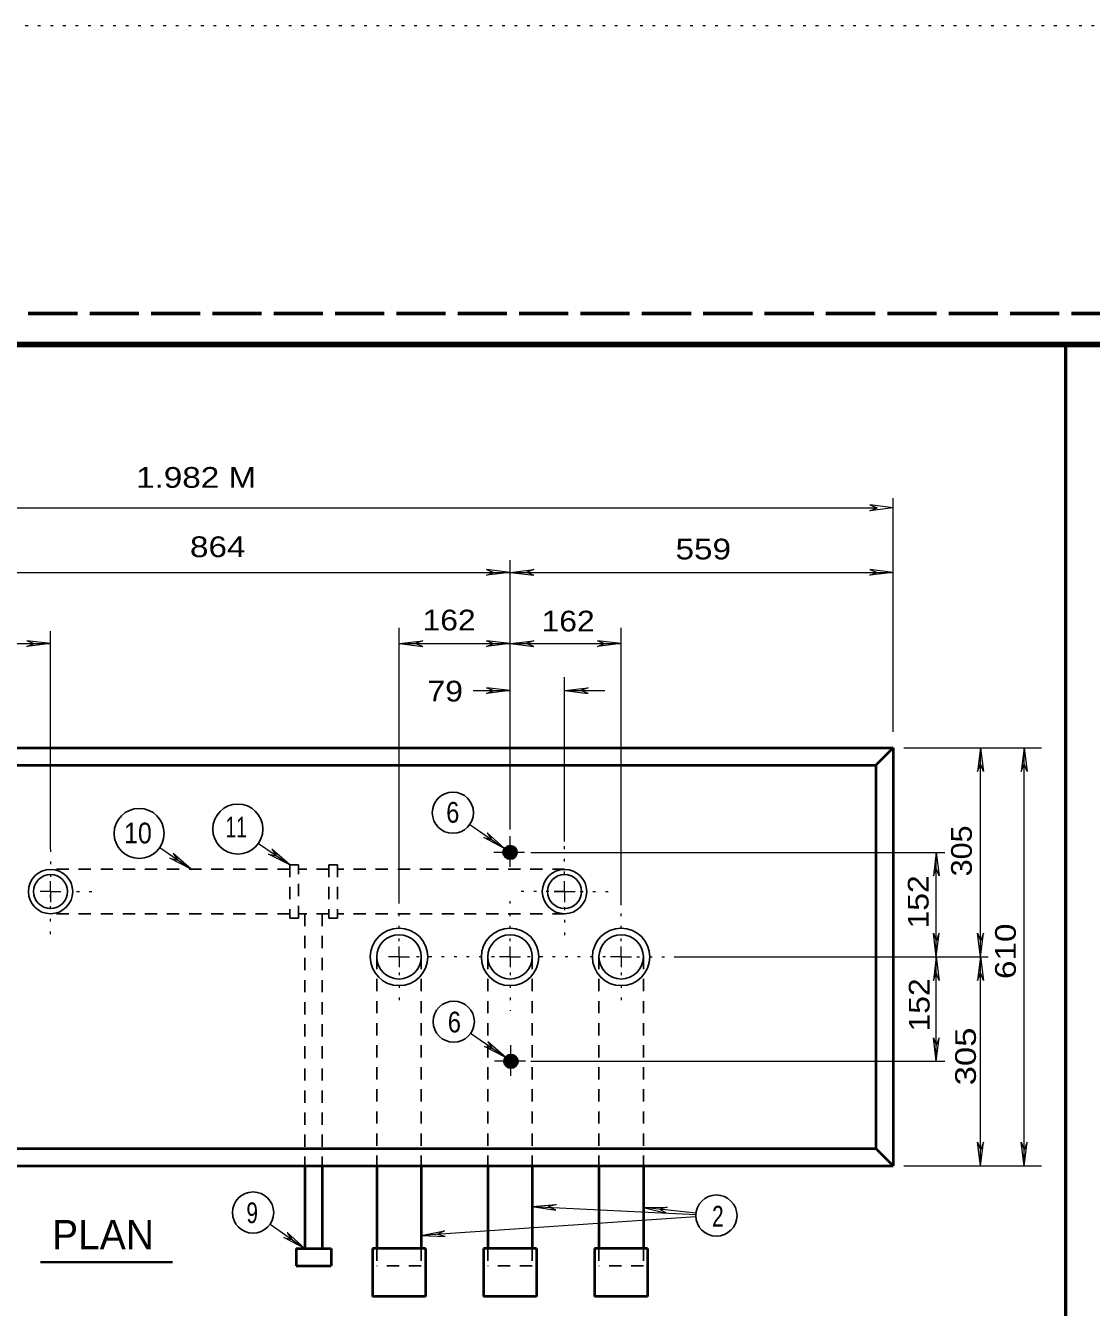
# Model space of a CAD drawing. Extents: x 312583 to 312854, y 144419 to 144597.
# Drawn here: x 312674.35 to 312713.43, y 144549.76 to 144596.78 of the extents above; entities that cross this region are included whole.
import ezdxf
from ezdxf.enums import TextEntityAlignment as Align

# ---------------------------------------------------------------- set-up
doc = ezdxf.new("R2010")
doc.units = 0
doc.header["$LTSCALE"] = 0.3
for name, pattern in [('DOTTED', [1.5, 0.3, -1.2]), ('LONG_DASHED', [7.5, 6, -1.5]), ('SHORT_DASHED', [2.7, 1.5, -1.2])]:
    doc.linetypes.add(name, pattern=pattern)
for name, color, linetype, lineweight in [('1', 7, 'Continuous', 25), ('2', 7, 'Continuous', 13), ('63', 7, 'DOTTED', 13)]:
    doc.layers.add(name, color=color, linetype=linetype, lineweight=lineweight)

msp = doc.modelspace()

# ---------------------------------------------------------------- linework, layer by layer
at = {"layer": '1', "linetype": 'LONG_DASHED', "lineweight": 60}
msp.add_line((312851.75, 144586.2246), (312583.526, 144586.2246), dxfattribs=at)
at = {"layer": '1', "lineweight": 53}
msp.add_line((312712.4965, 144506.4889), (312712.4965, 144585.0846), dxfattribs=at)
at = {"layer": '1', "lineweight": 40}
for p, q in [((312656.3351, 144570.2833), (312706.1684, 144570.2833)), ((312705.5321, 144569.6469), (312706.1684, 144570.2833)), ((312706.1684, 144570.2833), (312706.1684, 144554.9499)), ((312656.9791, 144569.6469), (312705.5321, 144569.6469)), ((312705.5321, 144569.6469), (312705.5321, 144555.5863)), ((312656.9791, 144555.5863), (312705.5321, 144555.5863)), ((312705.5321, 144555.5863), (312706.1684, 144554.9499)), ((312656.3351, 144554.9499), (312706.1684, 144554.9499)), ((312684.5944, 144554.9499), (312684.5944, 144551.9139)), ((312685.2307, 144554.9499), (312685.2307, 144551.9139)), ((312687.2317, 144554.9499), (312687.2317, 144551.9139)), ((312688.8571, 144554.9499), (312688.8571, 144551.9139)), ((312691.3027, 144554.9499), (312691.3027, 144551.9139)), ((312692.9281, 144554.9499), (312692.9281, 144551.9139)), ((312695.3737, 144554.9499), (312695.3737, 144551.9139)), ((312697.0067, 144554.9499), (312697.0067, 144551.9139)), ((312684.2724, 144551.9139), (312685.5527, 144551.9139)), ((312684.2724, 144551.9139), (312684.2724, 144551.2776)), ((312685.5527, 144551.9139), (312685.5527, 144551.2776)), ((312687.0707, 144551.9139), (312687.0707, 144550.1583)), ((312689.0181, 144551.9139), (312687.0707, 144551.9139)), ((312689.0181, 144551.9139), (312689.0181, 144550.1583)), ((312691.1417, 144551.9139), (312691.1417, 144550.1583)), ((312693.0891, 144551.9139), (312691.1417, 144551.9139)), ((312693.0891, 144551.9139), (312693.0891, 144550.1583)), ((312695.2127, 144551.9139), (312695.2127, 144550.1583)), ((312697.1601, 144551.9139), (312695.2127, 144551.9139)), ((312697.1601, 144551.9139), (312697.1601, 144550.1583)), ((312684.2724, 144551.2776), (312685.5527, 144551.2776)), ((312689.0181, 144550.1583), (312687.0707, 144550.1583)), ((312693.0891, 144550.1583), (312691.1417, 144550.1583)), ((312697.1601, 144550.1583), (312695.2127, 144550.1583))]:
    msp.add_line(p, q, dxfattribs=at)
at = {"layer": '1', "linetype": 'SHORT_DASHED'}
for p, q in [((312684.0347, 144565.8289), (312675.2641, 144565.8289)), ((312684.0347, 144565.9899), (312684.0347, 144564.0349)), ((312684.0347, 144565.9899), (312684.3567, 144565.9899)), ((312684.3567, 144565.9899), (312684.3567, 144565.8289)), ((312684.3567, 144564.0349), (312684.3567, 144565.8289)), ((312685.4684, 144565.8289), (312684.3567, 144565.8289)), ((312685.4684, 144565.9899), (312685.4684, 144564.1959)), ((312685.4684, 144565.9899), (312685.7904, 144565.9899)), ((312685.7904, 144565.9899), (312685.7904, 144564.0349)), ((312694.1164, 144565.8289), (312685.7904, 144565.8289)), ((312684.0347, 144564.1959), (312675.2641, 144564.1959)), ((312684.0347, 144564.0349), (312684.3567, 144564.0349)), ((312685.4684, 144564.1959), (312684.3567, 144564.1959)), ((312684.5944, 144564.1959), (312684.5944, 144554.9499)), ((312685.2307, 144564.1959), (312685.2307, 144554.9499)), ((312685.4684, 144564.0349), (312685.4684, 144564.1959)), ((312685.4684, 144564.0349), (312685.7904, 144564.0349)), ((312694.1164, 144564.1959), (312685.7904, 144564.1959)), ((312687.2317, 144562.6166), (312687.2317, 144554.9499)), ((312688.8571, 144562.6166), (312688.8571, 144554.9499)), ((312691.3027, 144562.6166), (312691.3027, 144554.9499)), ((312692.9281, 144562.6166), (312692.9281, 144554.9499)), ((312695.3737, 144562.6166), (312695.3737, 144554.9499)), ((312697.0067, 144562.6166), (312697.0067, 144554.9499)), ((312687.2317, 144551.9139), (312687.2317, 144551.2776)), ((312688.8571, 144551.9139), (312688.8571, 144551.2776)), ((312691.3027, 144551.9139), (312691.3027, 144551.2776)), ((312692.9281, 144551.9139), (312692.9281, 144551.2776)), ((312695.3737, 144551.9139), (312695.3737, 144551.2776)), ((312697.0067, 144551.9139), (312697.0067, 144551.2776)), ((312688.8571, 144551.2776), (312687.2317, 144551.2776)), ((312692.9281, 144551.2776), (312691.3027, 144551.2776)), ((312697.0067, 144551.2776), (312695.3737, 144551.2776))]:
    msp.add_line(p, q, dxfattribs=at)
at = {"layer": '1', "lineweight": 158}
msp.add_lwpolyline([(312616.5, 144423.1446), (312616.5, 144585.0846), (312849, 144585.0846)], dxfattribs=at)
at = {"layer": '1', "lineweight": 40}
for centre, radius in [((312692.116, 144566.4493), 0.2396), ((312692.116, 144566.4493), 0.2156), ((312692.116, 144566.4493), 0.1941), ((312692.116, 144566.4493), 0.1747), ((312692.116, 144566.4493), 0.1572), ((312692.116, 144566.4493), 0.1415), ((312692.116, 144566.4493), 0.1273), ((312692.116, 144566.4493), 0.1146), ((312692.116, 144566.4493), 0.1031), ((312692.116, 144566.4493), 0.0928), ((312692.116, 144566.4493), 0.0835), ((312692.116, 144566.4493), 0.0752), ((312692.116, 144566.4493), 0.0677), ((312692.116, 144566.4493), 0.0609), ((312692.116, 144566.4493), 0.0548), ((312692.148, 144558.7826), 0.2396), ((312692.148, 144558.7826), 0.2156), ((312692.148, 144558.7826), 0.1941), ((312692.148, 144558.7826), 0.1747), ((312692.148, 144558.7826), 0.1572), ((312692.148, 144558.7826), 0.1415), ((312692.148, 144558.7826), 0.1273), ((312692.148, 144558.7826), 0.1146), ((312692.148, 144558.7826), 0.1031), ((312692.148, 144558.7826), 0.0928), ((312692.148, 144558.7826), 0.0835), ((312692.148, 144558.7826), 0.0752), ((312692.148, 144558.7826), 0.0677), ((312692.148, 144558.7826), 0.0609), ((312692.148, 144558.7826), 0.0548)]:
    msp.add_circle(centre, radius, dxfattribs=at)
at = {"layer": '1'}
for centre, radius in [((312675.2653, 144565.0118), 0.8146), ((312694.1126, 144565.0118), 0.8146), ((312675.2653, 144565.0118), 0.6232), ((312694.1126, 144565.0118), 0.6232), ((312688.0431, 144562.616), 1.0542), ((312692.116, 144562.616), 1.0542), ((312696.189, 144562.616), 1.0542), ((312688.0431, 144562.616), 0.8146), ((312692.116, 144562.616), 0.8146), ((312696.189, 144562.616), 0.8146)]:
    msp.add_circle(centre, radius, dxfattribs=at)
at = {"layer": '2'}
for p, q in [((312706.1684, 144570.8736), (312706.1684, 144579.4526)), ((312656.3351, 144579.0923), (312705.5321, 144579.0923)), ((312705.3021, 144579.1996), (312705.5781, 144579.0923)), ((312706.1684, 144579.0923), (312705.3021, 144579.1996)), ((312705.3021, 144578.9849), (312705.5781, 144579.0923)), ((312706.1684, 144579.0923), (312705.3021, 144578.9849)), ((312692.1154, 144567.2856), (312692.1154, 144577.1679)), ((312670.3957, 144576.7233), (312692.1154, 144576.7233)), ((312691.2491, 144576.8306), (312691.5251, 144576.7233)), ((312692.1154, 144576.7233), (312691.2491, 144576.8306)), ((312691.2491, 144576.6159), (312691.5251, 144576.7233)), ((312692.1154, 144576.7233), (312691.2491, 144576.6159)), ((312692.1154, 144576.7233), (312692.9817, 144576.8306)), ((312692.1154, 144576.7233), (312706.1684, 144576.7233)), ((312692.1154, 144576.7233), (312692.9817, 144576.6159)), ((312692.9817, 144576.8306), (312692.7057, 144576.7233)), ((312692.9817, 144576.6159), (312692.7057, 144576.7233)), ((312705.3021, 144576.8306), (312705.5781, 144576.7233)), ((312706.1684, 144576.7233), (312705.3021, 144576.8306)), ((312705.3021, 144576.6159), (312705.5781, 144576.7233)), ((312706.1684, 144576.7233), (312705.3021, 144576.6159)), ((312675.2641, 144566.5726), (312675.2641, 144574.5613)), ((312688.0444, 144564.6023), (312688.0444, 144574.6916)), ((312696.1864, 144564.5179), (312696.1864, 144574.6916)), ((312670.3957, 144574.1089), (312675.2641, 144574.1089)), ((312674.3977, 144574.2163), (312674.6737, 144574.1089)), ((312675.2641, 144574.1089), (312674.3977, 144574.2163)), ((312674.3977, 144574.0016), (312674.6737, 144574.1089)), ((312675.2641, 144574.1089), (312674.3977, 144574.0016)), ((312688.0444, 144574.1089), (312688.9107, 144574.2163)), ((312688.0444, 144574.1089), (312688.9107, 144574.0016)), ((312688.0444, 144574.1089), (312692.1154, 144574.1089)), ((312688.9107, 144574.2163), (312688.6347, 144574.1089)), ((312688.9107, 144574.0016), (312688.6347, 144574.1089)), ((312691.2491, 144574.2163), (312691.5251, 144574.1089)), ((312692.1154, 144574.1089), (312691.2491, 144574.2163)), ((312691.2491, 144574.0016), (312691.5251, 144574.1089)), ((312692.1154, 144574.1089), (312691.2491, 144574.0016)), ((312692.1154, 144574.1089), (312692.9817, 144574.2163)), ((312692.1154, 144574.1089), (312696.1864, 144574.1089)), ((312692.1154, 144574.1089), (312692.9817, 144574.0016)), ((312692.9817, 144574.2163), (312692.7057, 144574.1089)), ((312692.9817, 144574.0016), (312692.7057, 144574.1089)), ((312695.3201, 144574.2163), (312695.5961, 144574.1089)), ((312696.1864, 144574.1089), (312695.3201, 144574.2163)), ((312695.3201, 144574.0016), (312695.5961, 144574.1089)), ((312696.1864, 144574.1089), (312695.3201, 144574.0016)), ((312694.1164, 144566.8486), (312694.1164, 144572.8823)), ((312691.2491, 144572.4913), (312691.5251, 144572.3839)), ((312692.1154, 144572.3839), (312691.2491, 144572.4913)), ((312694.1164, 144572.3839), (312694.9827, 144572.4913)), ((312694.9827, 144572.4913), (312694.7067, 144572.3839)), ((312690.7661, 144572.3839), (312692.1154, 144572.3839)), ((312691.2491, 144572.2766), (312691.5251, 144572.3839)), ((312692.1154, 144572.3839), (312691.2491, 144572.2766)), ((312694.1164, 144572.3839), (312695.5961, 144572.3839)), ((312694.1164, 144572.3839), (312694.9827, 144572.2766)), ((312694.9827, 144572.2766), (312694.7067, 144572.3839)), ((312706.5517, 144570.2833), (312711.5994, 144570.2833)), ((312709.3687, 144570.2833), (312709.2614, 144569.4169)), ((312709.3687, 144570.2833), (312709.476, 144569.4169)), ((312710.9675, 144570.2833), (312710.8602, 144569.4169)), ((312710.9675, 144570.2833), (312711.0748, 144569.4169)), ((312710.9675, 144554.9499), (312710.9675, 144570.2833)), ((312709.2614, 144569.4169), (312709.3687, 144569.6929)), ((312709.476, 144569.4169), (312709.3687, 144569.6929)), ((312710.8602, 144569.4169), (312710.9675, 144569.6929)), ((312711.0748, 144569.4169), (312710.9675, 144569.6929)), ((312690.6357, 144567.4773), (312691.9161, 144566.5879)), ((312682.8847, 144566.7796), (312684.0347, 144565.9899)), ((312691.1494, 144566.9943), (312691.4331, 144566.9253)), ((312691.9161, 144566.5879), (312691.1494, 144566.9943)), ((312691.2721, 144567.1706), (312691.4331, 144566.9253)), ((312691.9161, 144566.5879), (312691.2721, 144567.1706)), ((312692.1154, 144565.9209), (312692.1154, 144567.0479)), ((312679.2661, 144566.6263), (312680.4161, 144565.8289)), ((312679.7644, 144566.4116), (312679.9331, 144566.1663)), ((312680.4161, 144565.8289), (312679.7644, 144566.4116)), ((312683.2604, 144566.3886), (312683.5517, 144566.3196)), ((312684.0347, 144565.9899), (312683.2604, 144566.3886)), ((312683.3831, 144566.5649), (312683.5517, 144566.3196)), ((312684.0347, 144565.9899), (312683.3831, 144566.5649)), ((312692.6444, 144566.4499), (312691.5174, 144566.4499)), ((312692.8744, 144566.4499), (312708.0599, 144566.4499)), ((312707.7446, 144566.4499), (312707.6372, 144565.5836)), ((312707.7446, 144566.4499), (312707.8519, 144565.5836)), ((312679.6417, 144566.2353), (312679.9331, 144566.1663)), ((312680.4161, 144565.8289), (312679.6417, 144566.2353)), ((312707.6372, 144565.5836), (312707.7446, 144565.8596)), ((312707.8519, 144565.5836), (312707.7446, 144565.8596)), ((312675.2641, 144565.0086), (312675.2641, 144565.3919)), ((312694.1164, 144565.0086), (312694.1164, 144565.3919)), ((312675.2641, 144565.0086), (312674.8807, 144565.0086)), ((312675.2641, 144565.0086), (312675.6474, 144565.0086)), ((312675.2641, 144565.0086), (312675.2641, 144564.6253)), ((312694.1164, 144565.0086), (312694.4997, 144565.0086)), ((312694.1164, 144565.0086), (312694.1164, 144564.6253)), ((312707.6372, 144563.4829), (312707.7446, 144563.2069)), ((312707.7446, 144562.6166), (312707.6372, 144563.4829)), ((312707.8519, 144563.4829), (312707.7446, 144563.2069)), ((312707.7446, 144562.6166), (312707.8519, 144563.4829)), ((312709.2614, 144563.4829), (312709.3687, 144563.2069)), ((312709.3687, 144562.6166), (312709.2614, 144563.4829)), ((312709.476, 144563.4829), (312709.3687, 144563.2069)), ((312709.3687, 144562.6166), (312709.476, 144563.4829)), ((312688.0444, 144562.6166), (312688.0444, 144562.9999)), ((312692.1154, 144562.6166), (312692.1154, 144562.9999)), ((312696.1864, 144562.6166), (312696.1864, 144562.9999)), ((312688.0444, 144562.6166), (312687.6611, 144562.6166)), ((312688.0444, 144562.6166), (312688.4277, 144562.6166)), ((312688.0444, 144562.6166), (312688.0444, 144562.2333)), ((312692.1154, 144562.6166), (312691.7321, 144562.6166)), ((312692.1154, 144562.6166), (312692.4987, 144562.6166)), ((312692.1154, 144562.6166), (312692.1154, 144562.2333)), ((312696.1864, 144562.6166), (312695.8031, 144562.6166)), ((312696.1864, 144562.6166), (312696.5697, 144562.6166)), ((312696.1864, 144562.6166), (312696.1864, 144562.2333)), ((312698.1337, 144562.6166), (312709.6519, 144562.6166)), ((312707.7446, 144562.6166), (312707.6372, 144561.7503)), ((312707.7446, 144562.6166), (312707.8519, 144561.7503)), ((312709.3687, 144562.6166), (312709.2614, 144561.7503)), ((312709.3687, 144562.6166), (312709.476, 144561.7503)), ((312707.6372, 144561.7503), (312707.7446, 144562.0263)), ((312707.8519, 144561.7503), (312707.7446, 144562.0263)), ((312709.2614, 144561.7503), (312709.3687, 144562.0263)), ((312709.476, 144561.7503), (312709.3687, 144562.0263)), ((312690.6664, 144559.8106), (312691.9544, 144558.9213)), ((312691.1801, 144559.3276), (312691.4637, 144559.2586)), ((312691.9544, 144558.9213), (312691.1801, 144559.3276)), ((312691.3027, 144559.5039), (312691.4637, 144559.2586)), ((312691.9544, 144558.9213), (312691.3027, 144559.5039)), ((312692.1461, 144558.2543), (312692.1461, 144559.3813)), ((312707.6372, 144559.6496), (312707.7446, 144559.3736)), ((312707.7446, 144558.7833), (312707.6372, 144559.6496)), ((312707.8519, 144559.6496), (312707.7446, 144559.3736)), ((312707.7446, 144558.7833), (312707.8519, 144559.6496)), ((312692.6751, 144558.7833), (312691.5481, 144558.7833)), ((312692.8744, 144558.7833), (312708.0599, 144558.7833)), ((312709.2614, 144555.8163), (312709.3687, 144555.5403)), ((312709.3687, 144554.9499), (312709.2614, 144555.8163)), ((312709.476, 144555.8163), (312709.3687, 144555.5403)), ((312709.3687, 144554.9499), (312709.476, 144555.8163)), ((312710.8602, 144555.8163), (312710.9675, 144555.5403)), ((312710.9675, 144554.9499), (312710.8602, 144555.8163)), ((312710.8602, 144555.8163), (312710.9675, 144555.5403)), ((312710.9675, 144554.9499), (312710.8602, 144555.8163)), ((312711.0748, 144555.8163), (312710.9675, 144555.5403)), ((312710.9675, 144554.9499), (312711.0748, 144555.8163)), ((312711.0748, 144555.8163), (312710.9675, 144555.5403)), ((312710.9675, 144554.9499), (312711.0748, 144555.8163)), ((312706.5517, 144554.9499), (312711.5994, 144554.9499)), ((312692.9281, 144553.4626), (312693.8021, 144553.5316)), ((312692.9281, 144553.4626), (312698.9311, 144553.1636)), ((312692.9281, 144553.4626), (312693.7944, 144553.3169)), ((312693.8021, 144553.5316), (312693.5184, 144553.4396)), ((312693.7944, 144553.3169), (312693.5184, 144553.4396)), ((312697.0067, 144553.4166), (312697.8731, 144553.4319)), ((312698.9311, 144553.2096), (312697.0067, 144553.4166)), ((312697.0067, 144553.4166), (312697.8501, 144553.2173)), ((312697.8731, 144553.4319), (312697.5894, 144553.3553)), ((312697.8501, 144553.2173), (312697.5894, 144553.3553)), ((312683.3141, 144552.8033), (312684.5944, 144551.9139)), ((312698.9311, 144553.0716), (312688.8571, 144552.3969)), ((312683.8201, 144552.3203), (312684.1114, 144552.2513)), ((312684.5944, 144551.9139), (312683.8201, 144552.3203)), ((312683.9427, 144552.4966), (312684.1114, 144552.2513)), ((312684.5944, 144551.9139), (312683.9427, 144552.4966)), ((312688.8571, 144552.3969), (312689.7157, 144552.5656)), ((312688.8571, 144552.3969), (312689.7311, 144552.3509)), ((312689.7157, 144552.5656), (312689.4474, 144552.4353)), ((312689.7311, 144552.3509), (312689.4474, 144552.4353))]:
    msp.add_line(p, q, dxfattribs=at)
at = {"layer": '2', "linetype": 'DOTTED'}
for p, q in [((312694.1164, 144565.6526), (312694.1164, 144566.8486)), ((312675.2641, 144566.5726), (312675.2641, 144565.3919)), ((312675.2641, 144564.7863), (312675.2641, 144565.4686)), ((312676.2224, 144565.0086), (312676.8817, 144565.0086)), ((312693.5414, 144565.0086), (312692.3377, 144565.0086)), ((312694.6914, 144565.0086), (312695.8644, 144565.0086)), ((312675.2641, 144563.4523), (312675.2641, 144564.6253)), ((312688.0444, 144563.1916), (312688.0444, 144564.6023)), ((312692.1154, 144563.1916), (312692.1154, 144564.6636)), ((312694.1164, 144564.4336), (312694.1164, 144563.3449)), ((312696.1864, 144563.1916), (312696.1864, 144564.5179)), ((312691.5404, 144562.6166), (312688.6194, 144562.6166)), ((312695.6114, 144562.6166), (312692.7517, 144562.6166)), ((312696.7614, 144562.6166), (312698.1337, 144562.6166)), ((312688.0444, 144562.0416), (312688.0444, 144560.7459)), ((312692.1154, 144562.0416), (312692.1154, 144560.6309)), ((312696.1864, 144562.0416), (312696.1864, 144560.7153))]:
    msp.add_line(p, q, dxfattribs=at)
at = {"layer": '2', "lineweight": 25}
msp.add_line((312694.1164, 144565.0086), (312693.7331, 144565.0086), dxfattribs=at)
at = {"layer": '2', "lineweight": 35}
msp.add_line((312674.8964, 144551.4094), (312679.7414, 144551.4094), dxfattribs=at)
at = {"layer": '2'}
for points in [[(312709.3687, 144554.9499), (312709.3687, 144562.6166), (312709.3687, 144570.2833)], [(312707.7446, 144558.7833), (312707.7446, 144562.6166), (312707.7446, 144566.4499)]]:
    msp.add_lwpolyline(points, dxfattribs=at)
at = {"layer": '2', "lineweight": 25}
for centre, radius in [((312690.0173, 144567.906), 0.7557), ((312682.1321, 144567.306), 0.9185), ((312678.5128, 144567.1463), 0.9185), ((312690.0492, 144560.2393), 0.7557), ((312682.6911, 144553.2345), 0.7557), ((312699.6818, 144553.1234), 0.7557)]:
    msp.add_circle(centre, radius, dxfattribs=at)
at = {"layer": '63'}
msp.add_line((312601.2, 144596.7846), (312853.5, 144596.7846), dxfattribs=at)

# ---------------------------------------------------------------- texts
at = {"layer": '2'}
for s, width, p in [('1.982 M', 1.2, (312678.3998, 144579.8276)), ('864 ', 1.2, (312680.3773, 144577.2832)), ('559 ', 1.2, (312698.1824, 144577.1998)), ('162 ', 1.15, (312688.9043, 144574.5939)), ('162 ', 1.15, (312693.2681, 144574.5566)), ('79 ', 1.15, (312689.0876, 144571.9872)), ('6', 0.85, (312689.7744, 144567.5392)), ('11', 0.7, (312681.6776, 144566.9973)), ('10', 0.9, (312677.9605, 144566.7802)), ('6', 0.85, (312689.833, 144559.8444)), ('9', 0.75, (312682.4462, 144552.8465)), ('2', 0.75, (312699.5237, 144552.7205))]:
    msp.add_text(s, height=0.76, dxfattribs=dict(at, width=width)).set_placement(p)
for s, width, p in [('305', 1.1, (312709.048, 144565.5716)), ('152 ', 1.15, (312707.4614, 144563.6579)), ('610 ', 1.2, (312710.6607, 144561.8044)), ('152 ', 1.15, (312707.4987, 144559.8779)), ('305 ', 1.25, (312709.1974, 144557.9023))]:
    msp.add_text(s, height=0.76, rotation=90, dxfattribs=dict(at, width=width)).set_placement(p)
msp.add_text('PLAN', height=1.07, dxfattribs=at).set_placement((312677.1889, 144551.8909), align=Align.CENTER)

doc.saveas('drawing.dxf')
